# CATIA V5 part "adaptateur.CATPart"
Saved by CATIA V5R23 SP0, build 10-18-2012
Part number: adaptateur
Definition: adaptateur
Source: made
Bounding box of the stored display mesh (mm): x 0 to 34, y -29.957 to 29.957, z -30 to 30
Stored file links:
  C:\wamp\www\COURS\CONCEPTION GMP1\TITRE 01-CATIA VOLUMIQUE\05--ACTIONNEUR DE VANNE\prof\CORRECTION\Assemblage\adaptateur.CATPart
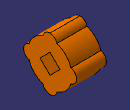
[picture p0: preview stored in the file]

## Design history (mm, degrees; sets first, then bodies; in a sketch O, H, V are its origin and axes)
Body1 "NONE" (main body)
  Solid1 "Manifold Solid #47": solid without history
